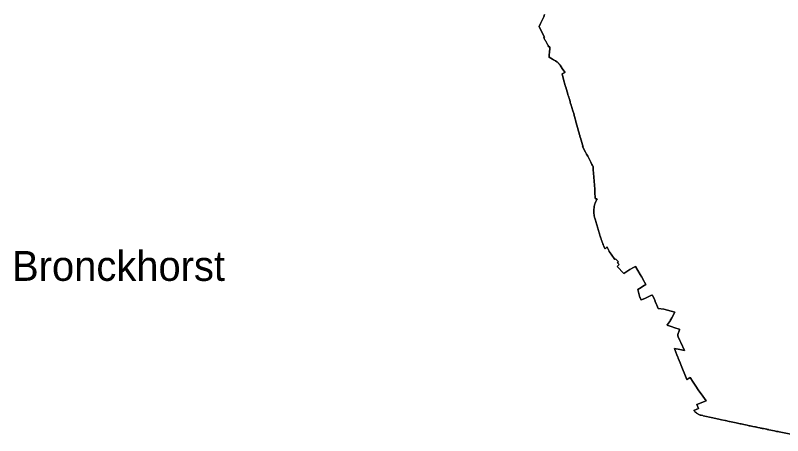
# Model space of a CAD drawing. Extents: x 113371 to 291721, y 393993 to 520143.
# Drawn here: x 215655 to 228510, y 448714 to 455750 of the extents above; entities that cross this region are included whole.
import ezdxf

# ---------------------------------------------------------------- set-up
doc = ezdxf.new("R2010")
doc.units = 0
doc.layers.add('Default', color=7, linetype='Continuous')
doc.layers.add('plaatsnamen', color=7, linetype='Continuous')

msp = doc.modelspace()

# ---------------------------------------------------------------- linework, layer by layer
at = {"layer": 'Default'}
for points in [[(224521.575625, 455763.4825), (224507.475625, 455722.9625), (224500.215625, 455704.4325), (224482.855625, 455668.7925), (224463.175625, 455635.5225), (224462.245625, 455633.9525), (224452.965625, 455614.6025), (224430.375625, 455563.0825), (224449.615625, 455524.5225), (224517.975625, 455387.7225), (224506.715625, 455379.8025), (224516.105625, 455361.6925), (224520.965625, 455354.2825), (224527.915625, 455343.2025), (224532.675625, 455334.9625), (224539.115625, 455324.4525), (224540.405625, 455319.5625), (224541.385625, 455317.8625), (224552.425625, 455298.7925), (224559.585625, 455286.2125), (224565.015625, 455276.3925), (224566.195625, 455274.2325)], [(224506.715625, 455379.8025), (224517.975625, 455387.7225), (224449.615625, 455524.5225), (224430.375625, 455563.0825), (224452.965625, 455614.6025), (224462.245625, 455633.9525), (224463.175625, 455635.5225), (224482.855625, 455668.7925), (224500.215625, 455704.4325), (224507.475625, 455722.9625), (224521.575625, 455763.4825)], [(224745.125625, 454960.3825), (224742.855625, 454962.7625), (224740.045625, 454964.9225), (224736.745625, 454966.4125), (224724.145625, 454974.0225), (224703.735625, 454986.3425), (224671.105625, 455005.6225), (224654.025625, 455015.9925), (224625.145625, 455033.4925), (224600.565625, 455047.8025), (224599.175625, 455047.2225), (224599.115625, 455053.5625), (224598.985625, 455055.8725), (224600.105625, 455055.6225), (224600.485625, 455070.3825), (224599.865625, 455070.5425), (224604.015625, 455151.6625), (224606.315625, 455156.6525), (224607.215625, 455174.1825), (224608.445625, 455197.4225), (224608.345625, 455215.9425), (224608.295625, 455224.8025), (224594.455625, 455223.1625), (224583.905625, 455242.4125), (224578.665625, 455251.7425), (224572.045625, 455263.5925), (224566.195625, 455274.2325), (224565.015625, 455276.3925), (224559.585625, 455286.2125), (224552.425625, 455298.7925), (224541.385625, 455317.8625), (224540.405625, 455319.5625), (224539.115625, 455324.4525), (224532.675625, 455334.9625), (224527.915625, 455343.2025), (224520.965625, 455354.2825), (224516.105625, 455361.6925), (224506.715625, 455379.8025)], [(224566.195625, 455274.2325), (224572.045625, 455263.5925), (224578.665625, 455251.7425), (224583.905625, 455242.4125), (224594.455625, 455223.1625), (224608.295625, 455224.8025), (224608.345625, 455215.9425), (224608.445625, 455197.4225), (224607.215625, 455174.1825), (224606.315625, 455156.6525), (224604.015625, 455151.6625), (224599.865625, 455070.5425), (224600.485625, 455070.3825), (224600.105625, 455055.6225), (224598.985625, 455055.8725), (224599.115625, 455053.5625), (224599.175625, 455047.2225), (224600.565625, 455047.8025), (224625.145625, 455033.4925), (224654.025625, 455015.9925), (224671.105625, 455005.6225), (224703.735625, 454986.3425), (224724.145625, 454974.0225), (224736.745625, 454966.4125), (224740.045625, 454964.9225), (224742.855625, 454962.7625), (224745.125625, 454960.3825), (224746.925625, 454957.6925), (224752.685625, 454948.3625), (224755.455625, 454944.8825), (224758.085625, 454941.6525), (224760.375625, 454939.4425), (224765.065625, 454935.3225), (224774.335625, 454927.4925), (224773.545625, 454927.1125), (224780.415625, 454916.0225), (224818.175625, 454859.4525), (224858.535625, 454796.7625)], [(225018.595625, 454073.1125), (225016.025625, 454081.5825), (225008.655625, 454105.4725), (224994.325625, 454153.3825), (224978.285625, 454207.9125), (224976.105625, 454215.3225), (224973.085625, 454225.6125), (224966.115625, 454249.3125), (224957.835625, 454277.4225), (224951.985625, 454297.2825), (224947.915625, 454311.0425), (224937.805625, 454345.2325), (224933.285625, 454360.6825), (224926.575625, 454382.3725), (224922.325625, 454395.3925), (224918.455625, 454407.4925), (224913.475625, 454421.5525), (224909.545625, 454432.0025), (224910.405625, 454432.2425), (224875.485625, 454548.9225), (224873.415625, 454555.8825), (224871.355625, 454562.7725), (224867.685625, 454575.0425), (224840.545625, 454678.3525), (224816.005625, 454771.7425), (224861.785625, 454794.3625), (224858.535625, 454796.7625), (224818.175625, 454859.4525), (224780.415625, 454916.0225), (224773.545625, 454927.1125), (224774.335625, 454927.4925), (224765.065625, 454935.3225), (224760.375625, 454939.4425), (224758.085625, 454941.6525), (224755.455625, 454944.8825), (224752.685625, 454948.3625), (224746.925625, 454957.6925), (224745.125625, 454960.3825)], [(224858.535625, 454796.7625), (224861.785625, 454794.3625), (224816.005625, 454771.7425), (224840.545625, 454678.3525), (224867.685625, 454575.0425), (224871.355625, 454562.7725), (224873.415625, 454555.8825), (224875.485625, 454548.9225), (224910.405625, 454432.2425), (224909.545625, 454432.0025), (224913.475625, 454421.5525), (224918.455625, 454407.4925), (224922.325625, 454395.3925), (224926.575625, 454382.3725), (224933.285625, 454360.6825), (224937.805625, 454345.2325), (224947.915625, 454311.0425), (224951.985625, 454297.2825), (224957.835625, 454277.4225), (224966.115625, 454249.3125), (224973.085625, 454225.6125), (224976.105625, 454215.3225), (224978.285625, 454207.9125), (224994.325625, 454153.3825), (225008.655625, 454105.4725), (225016.025625, 454081.5825), (225018.595625, 454073.1125), (225023.265625, 454057.6525), (225027.165625, 454041.9425), (225029.445625, 454032.9925), (225044.805625, 453976.4525), (225046.975625, 453968.4425), (225051.075625, 453953.3525), (225083.505625, 453834.0225), (225085.085625, 453828.1825), (225098.815625, 453779.5025), (225102.325625, 453767.0225), (225109.455625, 453741.7525)], [(225363.045625, 452820.8625), (225361.455625, 452841.9525), (225341.455625, 453108.3825), (225339.745625, 453126.5725), (225337.815625, 453147.0725), (225334.525625, 453208.1525), (225333.075625, 453217.4925), (225332.435625, 453219.5425), (225330.605625, 453225.4125), (225324.265625, 453237.3925), (225314.935625, 453254.4425), (225301.685625, 453278.8825), (225297.075625, 453287.7725), (225295.965625, 453289.9225), (225272.765625, 453334.6725), (225243.875625, 453390.4225), (225225.435625, 453425.9925), (225214.765625, 453446.5925), (225213.215625, 453449.5725), (225209.105625, 453457.5025), (225169.025625, 453534.8425), (225158.695625, 453554.7625), (225166.305625, 453544.2525), (225121.455625, 453699.2025), (225118.915625, 453708.1825), (225111.215625, 453735.5025), (225109.455625, 453741.7525), (225102.325625, 453767.0225), (225098.815625, 453779.5025), (225085.085625, 453828.1825), (225083.505625, 453834.0225), (225051.075625, 453953.3525), (225046.975625, 453968.4425), (225044.805625, 453976.4525), (225029.445625, 454032.9925), (225027.165625, 454041.9425), (225023.265625, 454057.6525), (225018.595625, 454073.1125)], [(225109.455625, 453741.7525), (225111.215625, 453735.5025), (225118.915625, 453708.1825), (225121.455625, 453699.2025), (225166.305625, 453544.2525), (225158.695625, 453554.7625), (225169.025625, 453534.8425), (225209.105625, 453457.5025), (225213.215625, 453449.5725), (225214.765625, 453446.5925), (225225.435625, 453425.9925), (225243.875625, 453390.4225), (225272.765625, 453334.6725), (225295.965625, 453289.9225), (225297.075625, 453287.7725), (225301.685625, 453278.8825), (225314.935625, 453254.4425), (225324.265625, 453237.3925), (225330.605625, 453225.4125), (225332.435625, 453219.5425), (225333.075625, 453217.4925), (225334.525625, 453208.1525), (225337.815625, 453147.0725), (225339.745625, 453126.5725), (225341.455625, 453108.3825), (225361.455625, 452841.9525), (225363.045625, 452820.8625), (225360.595625, 452816.0025), (225362.635625, 452783.7625), (225368.175625, 452696.3125), (225368.865625, 452685.4425), (225380.525625, 452682.2925), (225400.845625, 452676.7925), (225392.935625, 452663.7025), (225389.335625, 452656.1525), (225384.135625, 452644.9325), (225378.735625, 452632.6925), (225373.145625, 452617.9525)], [(225366.665625, 452339.0125), (225361.245625, 452356.4625), (225358.525625, 452366.8125), (225356.015625, 452377.5625), (225353.885625, 452390.9725), (225351.335625, 452405.1825), (225349.205625, 452418.3825), (225348.485625, 452426.2525), (225348.325625, 452427.9325), (225347.205625, 452442.3625), (225346.715625, 452453.7425), (225346.265625, 452466.6625), (225346.245625, 452467.3225), (225346.195625, 452468.5825), (225346.505625, 452482.0025), (225346.725625, 452485.7625), (225347.095625, 452491.7025), (225347.415625, 452497.0525), (225348.525625, 452511.9025), (225349.855625, 452524.3125), (225351.785625, 452537.7525), (225354.335625, 452550.9825), (225359.845625, 452574.8125), (225365.585625, 452596.2025), (225369.765625, 452608.6325), (225370.405625, 452610.3925), (225373.145625, 452617.9525), (225378.735625, 452632.6925), (225384.135625, 452644.9325), (225389.335625, 452656.1525), (225392.935625, 452663.7025), (225400.845625, 452676.7925), (225380.525625, 452682.2925), (225368.865625, 452685.4425), (225368.175625, 452696.3125), (225362.635625, 452783.7625), (225360.595625, 452816.0025), (225363.045625, 452820.8625)], [(225373.145625, 452617.9525), (225370.405625, 452610.3925), (225369.765625, 452608.6325), (225365.585625, 452596.2025), (225359.845625, 452574.8125), (225354.335625, 452550.9825), (225351.785625, 452537.7525), (225349.855625, 452524.3125), (225348.525625, 452511.9025), (225347.415625, 452497.0525), (225347.095625, 452491.7025), (225346.725625, 452485.7625), (225346.505625, 452482.0025), (225346.195625, 452468.5825), (225346.245625, 452467.3225), (225346.265625, 452466.6625), (225346.715625, 452453.7425), (225347.205625, 452442.3625), (225348.325625, 452427.9325), (225348.485625, 452426.2525), (225349.205625, 452418.3825), (225351.335625, 452405.1825), (225353.885625, 452390.9725), (225356.015625, 452377.5625), (225358.525625, 452366.8125), (225361.245625, 452356.4625), (225366.665625, 452339.0125), (225372.075625, 452321.1625), (225378.125625, 452300.6725), (225384.165625, 452280.9925), (225390.205625, 452260.7125), (225395.815625, 452243.8725), (225401.445625, 452224.1925), (225406.455625, 452205.9325), (225412.085625, 452186.6625), (225417.715625, 452167.5925), (225423.755625, 452148.1125), (225430.005625, 452127.8725)], [(225568.935625, 451868.1325), (225567.715625, 451870.5425), (225563.505625, 451867.0825), (225554.325625, 451859.5025), (225533.865625, 451843.1625), (225530.555625, 451848.4825), (225521.375625, 451869.0025), (225513.015625, 451887.4925), (225504.235625, 451907.8125), (225500.395625, 451917.7025), (225498.825625, 451921.7325), (225495.875625, 451929.3525), (225486.285625, 451952.5125), (225477.505625, 451975.4725), (225472.805625, 451988.4825), (225469.485625, 451998.1825), (225468.505625, 452001.0425), (225466.685625, 452006.3625), (225462.185625, 452021.8125), (225453.325625, 452051.7625), (225448.535625, 452067.1725), (225446.015625, 452075.7125), (225445.575625, 452077.2025), (225442.075625, 452089.0825), (225434.375625, 452113.2225), (225431.245625, 452123.9725), (225430.005625, 452127.8725), (225423.755625, 452148.1125), (225417.715625, 452167.5925), (225412.085625, 452186.6625), (225406.455625, 452205.9325), (225401.445625, 452224.1925), (225395.815625, 452243.8725), (225390.205625, 452260.7125), (225384.165625, 452280.9925), (225378.125625, 452300.6725), (225372.075625, 452321.1625), (225366.665625, 452339.0125)], [(225430.005625, 452127.8725), (225431.245625, 452123.9725), (225434.375625, 452113.2225), (225442.075625, 452089.0825), (225445.575625, 452077.2025), (225446.015625, 452075.7125), (225448.535625, 452067.1725), (225453.325625, 452051.7625), (225462.185625, 452021.8125), (225466.685625, 452006.3625), (225468.505625, 452001.0425), (225469.485625, 451998.1825), (225472.805625, 451988.4825), (225477.505625, 451975.4725), (225486.285625, 451952.5125), (225495.875625, 451929.3525), (225498.825625, 451921.7325), (225500.395625, 451917.7025), (225504.235625, 451907.8125), (225513.015625, 451887.4925), (225521.375625, 451869.0025), (225530.555625, 451848.4825), (225533.865625, 451843.1625), (225554.325625, 451859.5025), (225563.505625, 451867.0825), (225567.715625, 451870.5425), (225568.935625, 451868.1325), (225577.925625, 451850.2725), (225580.435625, 451845.2925), (225602.325625, 451801.8625), (225605.145625, 451797.7325), (225637.685625, 451750.2525), (225696.665625, 451664.2025), (225710.695625, 451675.4825), (225749.215625, 451634.3825), (225749.455625, 451634.1225), (225757.985625, 451625.0225), (225751.755625, 451617.6825)], [(226147.275625, 450987.4425), (226140.925625, 450984.5225), (226139.145625, 450987.0225), (226135.595625, 450994.6325), (226125.425625, 451015.4825), (226124.425625, 451017.7525), (226121.235625, 451024.9725), (226119.395625, 451028.9825), (226083.375625, 451158.6325), (226109.165625, 451175.4925), (226187.035625, 451226.4225), (226217.855625, 451246.5725), (226166.695625, 451333.4925), (226160.215625, 451348.2925), (226154.035625, 451362.5225), (226149.635625, 451369.7025), (226123.255625, 451412.9725), (226043.775625, 451543.3225), (226010.805625, 451526.4525), (225949.305625, 451494.4825), (225949.105625, 451494.3825), (225848.265625, 451426.7025), (225735.665625, 451546.1325), (225769.325625, 451577.4725), (225744.015625, 451608.5725), (225750.855625, 451616.6325), (225751.755625, 451617.6825), (225757.985625, 451625.0225), (225749.455625, 451634.1225), (225749.215625, 451634.3825), (225710.695625, 451675.4825), (225696.665625, 451664.2025), (225637.685625, 451750.2525), (225605.145625, 451797.7325), (225602.325625, 451801.8625), (225580.435625, 451845.2925), (225577.925625, 451850.2725), (225568.935625, 451868.1325)], [(225751.755625, 451617.6825), (225750.855625, 451616.6325), (225744.015625, 451608.5725), (225769.325625, 451577.4725), (225735.665625, 451546.1325), (225848.265625, 451426.7025), (225949.105625, 451494.3825), (225949.305625, 451494.4825), (226010.805625, 451526.4525), (226043.775625, 451543.3225), (226123.255625, 451412.9725), (226149.635625, 451369.7025), (226154.035625, 451362.5225), (226160.215625, 451348.2925), (226166.695625, 451333.4925), (226217.855625, 451246.5725), (226187.035625, 451226.4225), (226109.165625, 451175.4925), (226083.375625, 451158.6325), (226119.395625, 451028.9825), (226121.235625, 451024.9725), (226124.425625, 451017.7525), (226125.425625, 451015.4825), (226135.595625, 450994.6325), (226139.145625, 450987.0225), (226140.925625, 450984.5225), (226147.275625, 450987.4425), (226213.535625, 451017.7525), (226255.515625, 451038.6525), (226278.945625, 451050.3125), (226292.405625, 451056.6225), (226299.995625, 451060.2725), (226315.845625, 451067.1725), (226321.895625, 451069.8325), (226326.825625, 451061.4325), (226357.145625, 451009.9325), (226372.305625, 450967.0725), (226375.875625, 450957.2025)], [(226777.515625, 450495.5825), (226776.805625, 450495.9125), (226700.645625, 450521.1325), (226641.085625, 450540.8625), (226591.515625, 450556.8825), (226584.085625, 450559.4525), (226581.365625, 450561.1325), (226576.625625, 450565.9525), (226577.365625, 450574.9325), (226582.555625, 450575.7225), (226629.265625, 450640.9525), (226633.395625, 450646.8625), (226632.265625, 450651.0625), (226631.805625, 450653.1825), (226633.185625, 450655.9325), (226634.555625, 450658.4525), (226655.035625, 450687.8825), (226657.645625, 450692.1325), (226660.185625, 450696.8425), (226702.755625, 450782.3325), (226519.415625, 450834.0125), (226422.455625, 450840.4825), (226422.325625, 450840.7725), (226411.115625, 450868.3825), (226382.355625, 450939.6325), (226381.055625, 450942.8625), (226375.875625, 450957.2025), (226372.305625, 450967.0725), (226357.145625, 451009.9325), (226326.825625, 451061.4325), (226321.895625, 451069.8325), (226315.845625, 451067.1725), (226299.995625, 451060.2725), (226292.405625, 451056.6225), (226278.945625, 451050.3125), (226255.515625, 451038.6525), (226213.535625, 451017.7525), (226147.275625, 450987.4425)], [(226375.875625, 450957.2025), (226381.055625, 450942.8625), (226382.355625, 450939.6325), (226411.115625, 450868.3825), (226422.325625, 450840.7725), (226422.455625, 450840.4825), (226519.415625, 450834.0125), (226702.755625, 450782.3325), (226660.185625, 450696.8425), (226657.645625, 450692.1325), (226655.035625, 450687.8825), (226634.555625, 450658.4525), (226633.185625, 450655.9325), (226631.805625, 450653.1825), (226632.265625, 450651.0625), (226633.395625, 450646.8625), (226629.265625, 450640.9525), (226582.555625, 450575.7225), (226577.365625, 450574.9325), (226576.625625, 450565.9525), (226581.365625, 450561.1325), (226584.085625, 450559.4525), (226591.515625, 450556.8825), (226641.085625, 450540.8625), (226700.645625, 450521.1325), (226776.805625, 450495.9125), (226777.515625, 450495.5825), (226778.185625, 450495.1825), (226778.805625, 450494.7125), (226779.385625, 450494.1925), (226779.905625, 450493.6125), (226780.375625, 450492.9925), (226780.775625, 450492.3225), (226781.115625, 450491.6225), (226781.385625, 450490.8925), (226781.585625, 450490.1325), (226781.705625, 450489.3625), (226781.755625, 450488.5925)], [(226695.695625, 450171.9725), (226695.685625, 450172.0325), (226789.395625, 450155.9025), (226867.495625, 450140.8925), (226805.585625, 450273.2725), (226788.585625, 450308.9325), (226759.935625, 450369.6825), (226753.575625, 450384.4525), (226753.105625, 450385.6125), (226752.705625, 450386.7925), (226752.375625, 450388.0025), (226752.115625, 450389.2225), (226751.935625, 450390.4525), (226751.825625, 450391.7025), (226751.795625, 450392.9525), (226751.835625, 450394.2025), (226751.945625, 450395.4425), (226752.135625, 450396.6725), (226752.405625, 450397.8925), (226752.735625, 450399.0925), (226754.805625, 450406.0025), (226780.875625, 450484.8225), (226781.195625, 450485.5425), (226781.445625, 450486.2725), (226781.625625, 450487.0325), (226781.725625, 450487.8125), (226781.755625, 450488.5925), (226781.705625, 450489.3625), (226781.585625, 450490.1325), (226781.385625, 450490.8925), (226781.115625, 450491.6225), (226780.775625, 450492.3225), (226780.375625, 450492.9925), (226779.905625, 450493.6125), (226779.385625, 450494.1925), (226778.805625, 450494.7125), (226778.185625, 450495.1825), (226777.515625, 450495.5825)], [(226781.755625, 450488.5925), (226781.725625, 450487.8125), (226781.625625, 450487.0325), (226781.445625, 450486.2725), (226781.195625, 450485.5425), (226780.875625, 450484.8225), (226754.805625, 450406.0025), (226752.735625, 450399.0925), (226752.405625, 450397.8925), (226752.135625, 450396.6725), (226751.945625, 450395.4425), (226751.835625, 450394.2025), (226751.795625, 450392.9525), (226751.825625, 450391.7025), (226751.935625, 450390.4525), (226752.115625, 450389.2225), (226752.375625, 450388.0025), (226752.705625, 450386.7925), (226753.105625, 450385.6125), (226753.575625, 450384.4525), (226759.935625, 450369.6825), (226788.585625, 450308.9325), (226805.585625, 450273.2725), (226867.495625, 450140.8925), (226789.395625, 450155.9025), (226695.685625, 450172.0325), (226695.695625, 450171.9725), (226701.765625, 450155.6925), (226737.895625, 450064.6525), (226752.325625, 450030.4425), (226756.965625, 450017.7525), (226759.895625, 450009.7325), (226791.675625, 449931.9825), (226810.775625, 449886.1125), (226843.935625, 449806.4525), (226860.755625, 449765.4725), (226906.875625, 449653.0725), (226909.725625, 449654.9225)], [(227145.165625, 449055.0225), (227129.595625, 449058.5225), (227107.025625, 449068.5225), (227096.895625, 449073.5225), (227088.915625, 449078.3325), (227077.625625, 449085.3325), (227066.505625, 449093.0725), (227058.505625, 449099.0825), (227058.825625, 449099.5225), (227046.645625, 449109.3025), (227036.465625, 449118.2425), (227026.695625, 449127.9725), (227018.805625, 449136.5025), (227101.665625, 449167.3125), (227074.115625, 449234.2725), (227228.265625, 449297.8125), (227171.285625, 449375.4725), (227125.335625, 449438.0625), (227106.105625, 449465.5825), (227043.935625, 449559.7025), (227023.525625, 449591.7725), (227011.775625, 449610.2225), (226959.415625, 449686.8825), (226944.015625, 449676.9825), (226931.055625, 449668.6525), (226917.745625, 449660.1225), (226909.725625, 449654.9225), (226906.875625, 449653.0725), (226860.755625, 449765.4725), (226843.935625, 449806.4525), (226810.775625, 449886.1125), (226791.675625, 449931.9825), (226759.895625, 450009.7325), (226756.965625, 450017.7525), (226752.325625, 450030.4425), (226737.895625, 450064.6525), (226701.765625, 450155.6925), (226695.695625, 450171.9725)], [(226909.725625, 449654.9225), (226917.745625, 449660.1225), (226931.055625, 449668.6525), (226944.015625, 449676.9825), (226959.415625, 449686.8825), (227011.775625, 449610.2225), (227023.525625, 449591.7725), (227043.935625, 449559.7025), (227106.105625, 449465.5825), (227125.335625, 449438.0625), (227171.285625, 449375.4725), (227228.265625, 449297.8125), (227074.115625, 449234.2725), (227101.665625, 449167.3125), (227018.805625, 449136.5025), (227026.695625, 449127.9725), (227036.465625, 449118.2425), (227046.645625, 449109.3025), (227058.825625, 449099.5225), (227058.505625, 449099.0825), (227066.505625, 449093.0725), (227077.625625, 449085.3325), (227088.915625, 449078.3325), (227096.895625, 449073.5225), (227107.025625, 449068.5225), (227129.595625, 449058.5225), (227145.165625, 449055.0225)], [(227145.165625, 449055.0225), (227173.085625, 449048.7425), (227176.675625, 449047.9325), (227337.965625, 449011.6125), (227464.615625, 448983.0925), (227482.415625, 448979.4325), (227545.775625, 448966.2125), (227551.605625, 448964.9925), (227552.545625, 448966.6325), (227616.085625, 448952.4425), (227621.795625, 448951.2125), (227704.575625, 448933.4525), (227729.405625, 448928.1225), (227796.325625, 448913.6425), (227802.265625, 448912.3625), (227813.315625, 448909.9425), (227839.035625, 448904.3725), (227861.735625, 448899.7525), (227915.295625, 448888.2925), (227948.005625, 448880.7025), (227952.355625, 448879.9425), (227952.835625, 448879.8625), (227963.175625, 448878.1125), (227966.565625, 448876.5025), (227985.075625, 448872.6325), (228011.605625, 448867.7425), (228042.715625, 448861.1725), (228053.825625, 448859.1225), (228071.635625, 448855.8425), (228072.925625, 448855.3125), (228074.215625, 448854.7925), (228094.765625, 448850.8125), (228129.255625, 448843.3825), (228139.625625, 448841.3925), (228144.825625, 448840.6925), (228150.555625, 448839.5625), (228156.325625, 448838.4225), (228167.155625, 448836.2825)], [(228167.155625, 448836.2825), (228156.325625, 448838.4225), (228150.555625, 448839.5625), (228144.825625, 448840.6925), (228139.625625, 448841.3925), (228129.255625, 448843.3825), (228094.765625, 448850.8125), (228074.215625, 448854.7925), (228072.925625, 448855.3125), (228071.635625, 448855.8425), (228053.825625, 448859.1225), (228042.715625, 448861.1725), (228011.605625, 448867.7425), (227985.075625, 448872.6325), (227966.565625, 448876.5025), (227963.175625, 448878.1125), (227952.835625, 448879.8625), (227952.355625, 448879.9425), (227948.005625, 448880.7025), (227915.295625, 448888.2925), (227861.735625, 448899.7525), (227839.035625, 448904.3725), (227813.315625, 448909.9425), (227802.265625, 448912.3625), (227796.325625, 448913.6425), (227729.405625, 448928.1225), (227704.575625, 448933.4525), (227621.795625, 448951.2125), (227616.085625, 448952.4425), (227552.545625, 448966.6325), (227551.605625, 448964.9925), (227545.775625, 448966.2125), (227482.415625, 448979.4325), (227464.615625, 448983.0925), (227337.965625, 449011.6125), (227176.675625, 449047.9325), (227173.085625, 449048.7425), (227145.165625, 449055.0225)], [(228167.155625, 448836.2825), (228187.495625, 448831.7125), (228189.085625, 448831.5825), (228190.685625, 448831.4525), (228216.015625, 448826.1825), (228237.365625, 448821.9725), (228238.745625, 448821.7025), (228245.135625, 448820.4525), (228248.585625, 448819.7025), (228249.835625, 448819.4325), (228271.115625, 448814.8525), (228278.625625, 448813.2325), (228310.325625, 448806.4425), (228340.245625, 448800.4925), (228372.545625, 448793.5025), (228406.645625, 448786.2725), (228435.045625, 448782.1325), (228436.625625, 448781.9025), (228452.735625, 448778.5225), (228757.855625, 448714.1125)], [(228757.855625, 448714.1125), (228452.735625, 448778.5225), (228436.625625, 448781.9025), (228435.045625, 448782.1325), (228406.645625, 448786.2725), (228372.545625, 448793.5025), (228340.245625, 448800.4925), (228310.325625, 448806.4425), (228278.625625, 448813.2325), (228271.115625, 448814.8525), (228249.835625, 448819.4325), (228248.585625, 448819.7025), (228245.135625, 448820.4525), (228238.745625, 448821.7025), (228237.365625, 448821.9725), (228216.015625, 448826.1825), (228190.685625, 448831.4525), (228189.085625, 448831.5825), (228187.495625, 448831.7125), (228167.155625, 448836.2825)]]:
    msp.add_lwpolyline(points, dxfattribs=at)

# ---------------------------------------------------------------- texts
at = {"layer": 'plaatsnamen'}
msp.add_text('Bronckhorst', height=500, dxfattribs=at).set_placement((215600.183595, 451305.305608))

doc.saveas('drawing.dxf')
